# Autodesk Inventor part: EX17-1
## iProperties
Shininess: 64.0
Length Units: 11272
Angle Units: 11279
Time Units: 11290
Mass Units: 11286
Length Display Precision: 3
Compacted: True
Part Number: EX17-1
Document SubType Name: Modeling
Created: 2002-11
Designer: E. MOSS
Project: EVERGEEN COLLEGE
Description: U-JOINT
Authority: MS. TEACHER
Density: 0.0
Volumn: 0.0
Area: 0.0
PropertySet Name: Model Information
Control State: 0
Master: False
Checked Out: False
Author: E. MOSS
Revision Number: A
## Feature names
1. Sweep1
2. Revolution1
3. Mirror1
4. Hole1
5. Extrusion1
6. Fillet1
